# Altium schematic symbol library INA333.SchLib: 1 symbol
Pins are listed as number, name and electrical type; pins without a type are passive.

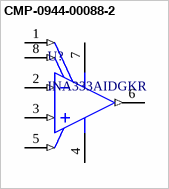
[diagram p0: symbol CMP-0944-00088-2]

## CMP-0944-00088-2
designator U?, comment INA333AIDGKR
Low Power, Precision Instrumentation Amplifier, -40 to 125 degC, 8-pin SOP (DGK8), Green (RoHS & no Sb/Br); Manufacturer: Texas Instruments; Input Offset Drift (+/-)(Max)(uV/Degrees Celsius): 0.1; Vs(Max)(V): 5.5; Input Bias Current (+/-)(Max)(nA): 0.2; Output Offset (+/-)(Max)(uV): 75/G; CMRR(Min)(dB): 100; Noise at 1kHz(Typ)(nV/rt(Hz)): 50; Output Offset Drift (+/-)(Max)(uV/Degrees Celsius): 0.5/G; Vs(Min)(V): 1.8; Quiescent Current (+/-)(Typ)(mA): 0.05; Gain(V/V): 1 to 1000; SubFamily: Single Supply; Number of Channels: 1; Input Offset (+/-)(Max)(uV): 25
footprint DGK0008A_M (TSOP, 8-Leads, Body 3.1x3.1mm, Pitch 0.65mm, IPC Low Density)
footprint DGK0008A_L (TSOP, 8-Leads, Body 3.1x3.1mm, Pitch 0.65mm, IPC High Density)
footprint DGK0008A_N (TSOP, 8-Leads, Body 3.1x3.1mm, Pitch 0.65mm, IPC Medium Density)
pins: 1 RG (in), 2 VIN- (in), 3 VIN+ (in), 4 V- (power), 5 REF (in), 6 VOUT (out), 7 V+ (power), 8 RG (in)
